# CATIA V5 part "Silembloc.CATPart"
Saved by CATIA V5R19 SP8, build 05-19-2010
Part number: Silembloc
Nomenclature: 53
Material "Caoutchouc": density 910 kg/m3, Young's modulus 2e+06 Pa, Poisson ratio 0.49, thermal expansion 0.000162 1/K
Material "Aluminium": density 2710 kg/m3, Young's modulus 7e+10 Pa, Poisson ratio 0.346, thermal expansion 2.36e-05 1/K
Material "Aluminium": density 2710 kg/m3, Young's modulus 7e+10 Pa, Poisson ratio 0.346, thermal expansion 2.36e-05 1/K
Bounding box of the stored display mesh (mm): x -12.75 to 12.75, y -12.75 to 12.75, z -13.5 to 15
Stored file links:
  C:\Users\rphgr\Desktop\0_Tapis_TC520B_vitesse\Silembloc.CATPart
  C:\Program Files\Dassault Systemes\B19\win_b64\reffiles\standard\MetricThickPitch.txt
  D:\Programmes\DassaultSysteme\win_b64\startup\materials\French\Catalog.CATMaterial
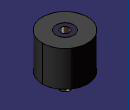
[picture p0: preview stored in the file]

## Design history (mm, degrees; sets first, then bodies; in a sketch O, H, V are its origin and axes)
AxisSystem1: origin (0, 0, 0), X (1, 0, 0), Y (0, 1, 0), Z (0, 0, 1)
Body1 (main body), material "Caoutchouc"
  Sketch1 on XY plane of AxisSystem1, origin (0, 0, 0), H (1, 0, 0), V (0, 1, 0)
    circle A1 centre (0, 0) radius 12.75
    radius A1 = 12.75
  Pad1: profile Sketch1, direction (0, 0, 1), length 15, opposite side length 5
  Body2 "Vis"
    Solid1: linked copy from another document
  Remove1: tool Body2
  Body3
    Solid2: linked copy from another document
  Remove2: tool Body3
  Sketch2 on end face of Pad1, origin (0, 0, 15), H (1, 0, 0), V (0, 1, 0)
    circle A1 centre (0, 0) radius 3.8663
    radius A1 = 3.8663
  Pocket1: profile Sketch2, direction (0, 0, -1), length 10
Body4 "Vis", material "Aluminium"
  Sketch3 on XY plane of AxisSystem1, origin (0, 0, 0), H (1, 0, 0), V (0, 1, 0)
    point P1 (7.5, -4.3301)
    point P2 (7.5, 4.3301)
    point P3 (0, 8.6603)
    point P4 (-7.5, 4.3301)
    point P5 (-7.5, -4.3301)
    point P6 (0, -8.6603)
    point P7 (7.5, 0)
    line L1 (7.5, -4.3301) -> (7.5, 4.3301)
    line L2 (7.5, 4.3301) -> (0, 8.6603)
    line L3 (0, 8.6603) -> (-7.5, 4.3301)
    line L4 (-7.5, 4.3301) -> (-7.5, -4.3301)
    line L5 (-7.5, -4.3301) -> (0, -8.6603)
    line L6 (0, -8.6603) -> (7.5, -4.3301)
    construction line L7 (0, 0) -> (7.5, 0)
    construction circle A1 centre (0, 0) radius 8.6603
    construction arc A2 centre (-7.5, -4.3301) radius 8.6603 from (-7.5, 4.3301) to (0, -8.6603) cw
    construction arc A3 centre (7.5, 4.3301) radius 8.6603 from (0, 8.6603) to (7.5, -4.3301) ccw
    distance L1 L4 = 15
    horizontal: L7 H
    coincidence: A1 P1, A1 P2, A1 P3, A1 P4, A1 P5, A1 P6, A2 O, A3 O
    midpoint: P7 L1
  Pad2: profile Sketch3, direction (0, 0, -1), length 3.5
  Sketch4 on end face of Pad2, origin (0, 0, -3.5), H (1, 0, 0), V (0, -1, 0)
    circle A1 centre (0, 0) radius 3
    radius A1 = 3
  Pad3: profile Sketch4, direction (0, 0, -1), length 10
  Thread1: diameter 6, depth 10, pitch 1, on face of Pad3 from Sketch4.A1, from end face of Pad3
  Chamfer1: length 0.5, angle 45, on edge [face of Pad3 from Sketch4.A1 | end face of Pad3]
Body5, material "Aluminium"
  Sketch5 on end face of Pad1, origin (0, 0, 15), H (1, 0, 0), V (0, 1, 0)
    circle A1 centre (0, 0) radius 5
    radius A1 = 5
  Pad4: profile Sketch5, direction (0, 0, -1), length 10
  Sketch6 on start face of Pad4, origin (0, 0, 15), H (1, 0, 0), V (0, 1, 0)
    point P1 (0, 0)
    reference projected point E1 (0, 0) from axis of face of Pad4 from Sketch5.A1
    coincidence: P1 E1
  Hole1: placed by Sketch6, at (0, 0, 15) direction (0, 0, -1), diameter 4.917, depth 5.27, threaded, thread diameter 6, thread depth 5, pitch 1
  Sketch7 on end face of Pad4, origin (0, 0, 5), H (1, 0, 0), V (0, -1, 0)
    point P1 (2.764, -8.663)
    point P2 (8.8844, -1.9378)
    point P3 (6.1204, 6.7252)
    point P4 (-2.764, 8.663)
    point P5 (-8.8844, 1.9378)
    point P6 (-6.1204, -6.7252)
    point P7 (5.8242, -5.3004)
    line L1 (2.764, -8.663) -> (8.8844, -1.9378)
    line L2 (8.8844, -1.9378) -> (6.1204, 6.7252)
    line L3 (6.1204, 6.7252) -> (-2.764, 8.663)
    line L4 (-2.764, 8.663) -> (-8.8844, 1.9378)
    line L5 (-8.8844, 1.9378) -> (-6.1204, -6.7252)
    line L6 (-6.1204, -6.7252) -> (2.764, -8.663)
    construction line L7 (0, 0) -> (5.8242, -5.3004)
    construction circle A1 centre (0, 0) radius 9.0933
    construction arc A2 centre (-8.8844, 1.9378) radius 9.0933 from (-2.764, 8.663) to (-6.1204, -6.7252) cw
    construction arc A3 centre (8.8844, -1.9378) radius 9.0933 from (6.1204, 6.7252) to (2.764, -8.663) ccw
    distance L2 L5 = 15.75
    coincidence: A1 P1, A1 P2, A1 P3, A1 P4, A1 P5, A1 P6, A2 O, A3 O
    midpoint: P7 L1
    parallelism: L1 L4
  Pad5: profile Sketch7, direction (0, 0, -1), length 2.55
